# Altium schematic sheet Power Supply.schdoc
size 594 x 419 mm; Symbol: Drawing-Symbol_A4; @Project Name: Inverted_MAML_6x6; @Page Count: 5; @Update Date: 2026-08-04; @Create Date: 2026-08-04; @Schematic Name: Inverted_MAML; @Page No: 5; @Page Name: P1; Company: EasyEDA.com; Version: V1.0; Page Size: A4; Device: Drawing-Symbol_A4; @Create Time: 19:32:30; @Update Time: 19:32:30; Border: 1; Width: 2338; Height: 1652; Region Start: 1; X Region Count: 6; Y Region Count: 4; Blade Width: 10; Title Block Position: 3; @Board Name: Analog_Matrix
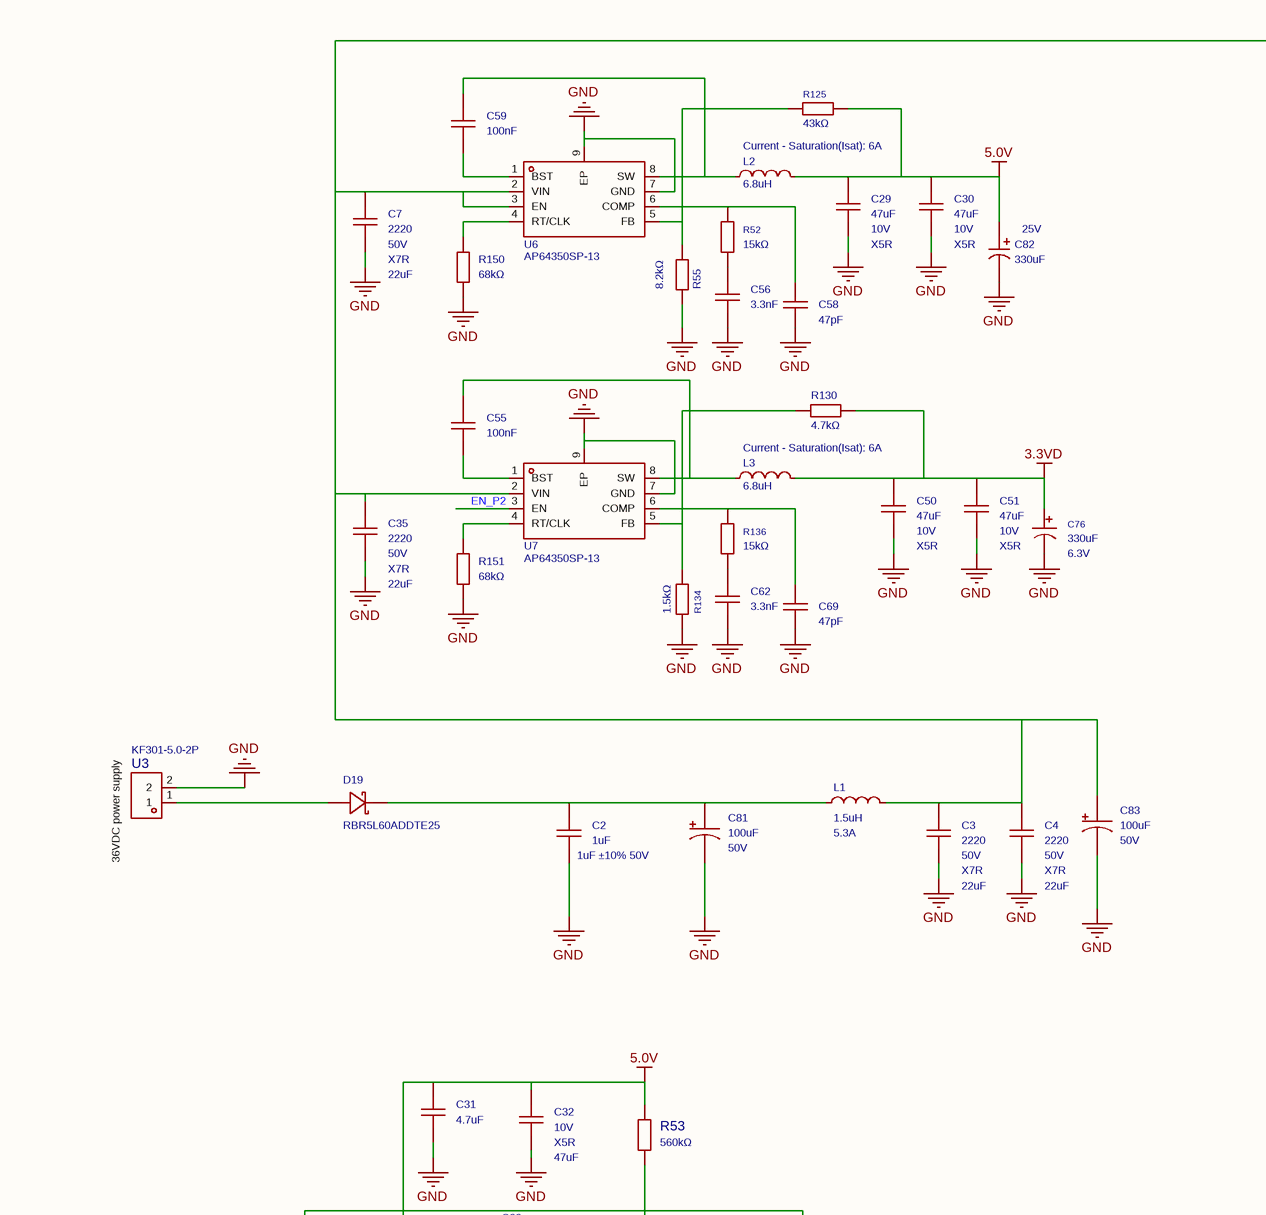
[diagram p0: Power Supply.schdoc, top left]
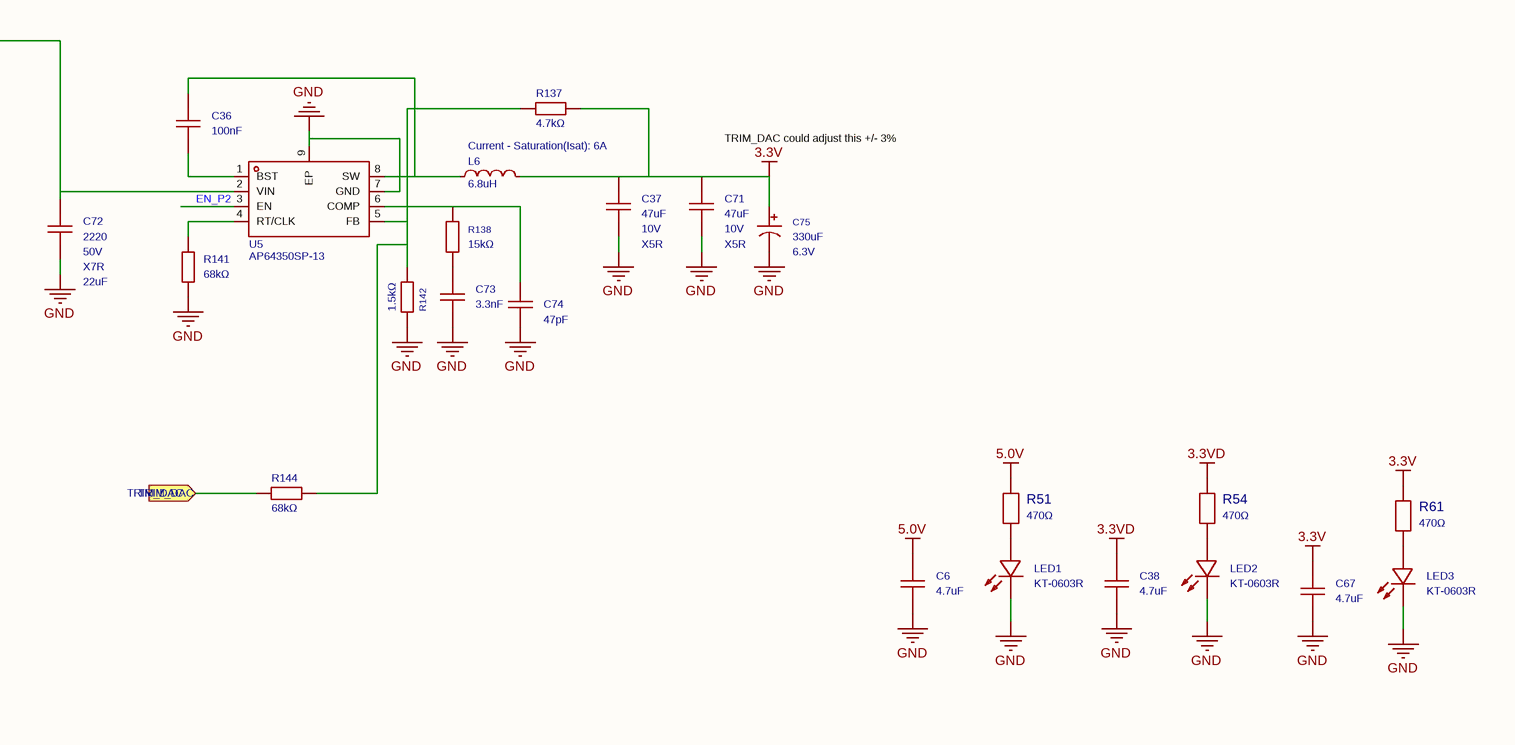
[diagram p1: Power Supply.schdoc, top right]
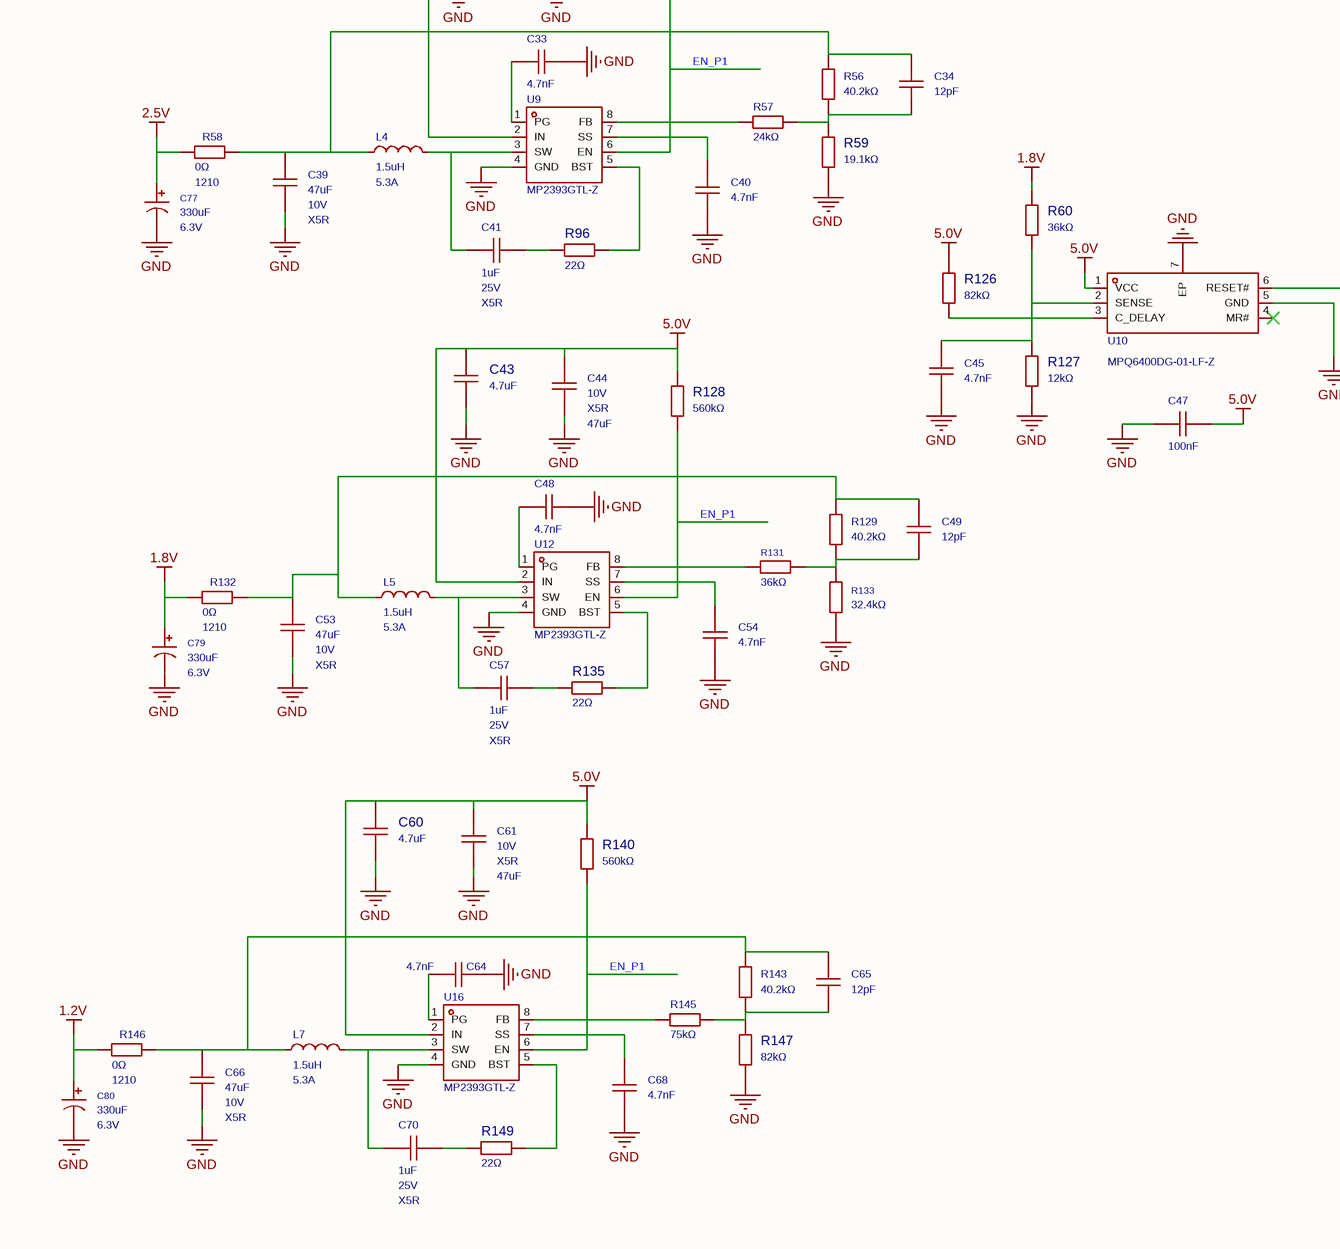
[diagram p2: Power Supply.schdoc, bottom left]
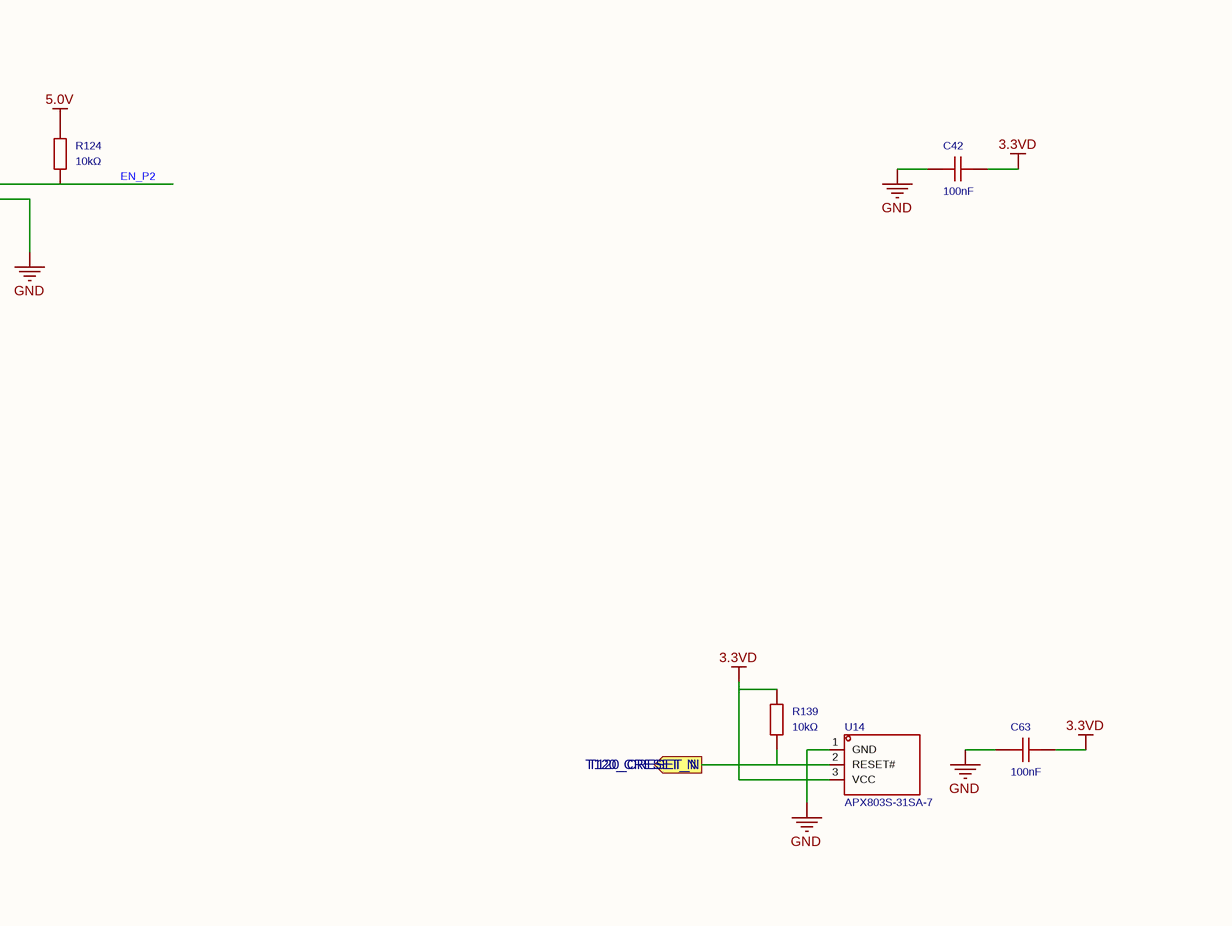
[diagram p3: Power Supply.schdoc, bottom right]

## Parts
C2  1uF  LCSC Part Name: 1uF ±10% 50V  [C1206]
C3  22uF  Supplier Footprint: 2220  Voltage Rating: 50V  Temperature Coefficient: X7R  [C2220]
C4  22uF  Supplier Footprint: 2220  Voltage Rating: 50V  Temperature Coefficient: X7R  [C2220]
C6  4.7uF  [C0402]
C7  22uF  Supplier Footprint: 2220  Voltage Rating: 50V  Temperature Coefficient: X7R  [C2220]
C29  47uF  Voltage Rating: 10V  Temperature Coefficient: X5R  [C1206]
C30  47uF  Voltage Rating: 10V  Temperature Coefficient: X5R  [C1206]
C31  4.7uF  [C0402]
C32  47uF  Voltage Rating: 10V  Temperature Coefficient: X5R  [C1206]
C33  4.7nF  [C0402]
C34  12pF  [C0402]
C35  22uF  Supplier Footprint: 2220  Voltage Rating: 50V  Temperature Coefficient: X7R  [C2220]
C36  100nF  [C0402]
C37  47uF  Voltage Rating: 10V  Temperature Coefficient: X5R  [C1206]
C38  4.7uF  [C0402]
C39  47uF  Voltage Rating: 10V  Temperature Coefficient: X5R  [C1206]
C40  4.7nF  [C0402]
C41  1uF  Voltage Rating: 25V  Temperature Coefficient: X5R  [C0402]
C42  100nF  [C0402]
C43  4.7uF  [C0402]
C44  47uF  Voltage Rating: 10V  Temperature Coefficient: X5R  [C1206]
C45  4.7nF  [C0402]
C47  100nF  [C0402]
C48  4.7nF  [C0402]
C49  12pF  [C0402]
C50  47uF  Voltage Rating: 10V  Temperature Coefficient: X5R  [C1206]
C51  47uF  Voltage Rating: 10V  Temperature Coefficient: X5R  [C1206]
C53  47uF  Voltage Rating: 10V  Temperature Coefficient: X5R  [C1206]
C54  4.7nF  [C0402]
C55  100nF  [C0402]
C56  3.3nF  [C0402]
C57  1uF  Voltage Rating: 25V  Temperature Coefficient: X5R  [C0402]
C58  47pF  [C0402]
C59  100nF  [C0402]
C60  4.7uF  [C0402]
C61  47uF  Voltage Rating: 10V  Temperature Coefficient: X5R  [C1206]
C62  3.3nF  [C0402]
C63  100nF  [C0402]
C64  4.7nF  [C0402]
C65  12pF  [C0402]
C66  47uF  Voltage Rating: 10V  Temperature Coefficient: X5R  [C1206]
C67  4.7uF  [C0402]
C68  4.7nF  [C0402]
C69  47pF  [C0402]
C70  1uF  Voltage Rating: 25V  Temperature Coefficient: X5R  [C0402]
C71  47uF  Voltage Rating: 10V  Temperature Coefficient: X5R  [C1206]
C72  22uF  Supplier Footprint: 2220  Voltage Rating: 50V  Temperature Coefficient: X7R  [C2220]
C73  3.3nF  [C0402]
C74  47pF  [C0402]
C75  330uF  Voltage Rating: 6.3V  [CAP-SMD_BD6.3-L6.6-W6.6-FD]
C76  330uF  Voltage Rating: 6.3V  [CAP-SMD_BD6.3-L6.6-W6.6-FD]
C77  330uF  Voltage Rating: 6.3V  [CAP-SMD_BD6.3-L6.6-W6.6-FD]
C79  330uF  Voltage Rating: 6.3V  [CAP-SMD_BD6.3-L6.6-W6.6-FD]
C80  330uF  Voltage Rating: 6.3V  [CAP-SMD_BD6.3-L6.6-W6.6-FD]
C81  100uF  Voltage Rating: 50V  [CAP-SMD_BD10.0-L10.3-W10.3-LS11.0-FD]
C82  330uF  Voltage Rating: 25V  [CAP-SMD_BD8.0-L8.3-W8.3-FD]
C83  100uF  Voltage Rating: 50V  [CAP-SMD_BD10.0-L10.3-W10.3-LS11.0-FD]
D19  RBR5L60ADDTE25  [SMA_L4.5-W2.6-LS5.0-RD]
L1  1.5uH  Current Rating: 5.3A  [IND-SMD_L7.8-W7.0_GCD75]
L2  6.8uH  Current - Saturation(Isat): 6A  [IND-SMD_L6.6-W6.6]
L3  6.8uH  Current - Saturation(Isat): 6A  [IND-SMD_L6.6-W6.6]
L4  1.5uH  Current Rating: 5.3A  [IND-SMD_L7.8-W7.0_GCD75]
L5  1.5uH  Current Rating: 5.3A  [IND-SMD_L7.8-W7.0_GCD75]
L6  6.8uH  Current - Saturation(Isat): 6A  [IND-SMD_L6.6-W6.6]
L7  1.5uH  Current Rating: 5.3A  [IND-SMD_L7.8-W7.0_GCD75]
LED1  KT-0603R  [LED0603-RD]
LED2  KT-0603R  [LED0603-RD]
LED3  KT-0603R  [LED0603-RD]
R51  470Ω  [R0402]
R52  15kΩ  [R0402]
R53  560kΩ  [R0402]
R54  470Ω  [R0402]
R55  8.2kΩ  [R0402]
R56  40.2kΩ  [R0402]
R57  24kΩ  [R0402]
R58  0Ω  Supplier Footprint: 1210  [R1210]
R59  19.1kΩ  [R0402]
R60  36kΩ  [R0402]
R61  470Ω  [R0402]
R96  22Ω  [R0402]
R124  10kΩ  [R0402]
R125  43kΩ  [R0402]
R126  82kΩ  [R0402]
R127  12kΩ  [R0402]
R128  560kΩ  [R0402]
R129  40.2kΩ  [R0402]
R130  4.7kΩ  [R0402]
R131  36kΩ  [R0402]
R132  0Ω  Supplier Footprint: 1210  [R1210]
R133  32.4kΩ  [R0402]
R134  1.5kΩ  [R0402]
R135  22Ω  [R0402]
R136  15kΩ  [R0402]
R137  4.7kΩ  [R0402]
R138  15kΩ  [R0402]
R139  10kΩ  [R0402]
R140  560kΩ  [R0402]
R141  68kΩ  [R0402]
R142  1.5kΩ  [R0402]
R143  40.2kΩ  [R0402]
R144  68kΩ  [R0402]
R145  75kΩ  [R0402]
R146  0Ω  Supplier Footprint: 1210  [R1210]
R147  82kΩ  [R0402]
R149  22Ω  [R0402]
R150  68kΩ  [R0402]
R151  68kΩ  [R0402]
U3  KF301-5.0-2P  [CONN-TH_P5.00_KF301-5.0-2P]
U5  AP64350SP-13  [SO-8_L4.9-W3.9-P1.27-LS6.0-BL-EP]
U6  AP64350SP-13  [SO-8_L4.9-W3.9-P1.27-LS6.0-BL-EP]
U7  AP64350SP-13  [SO-8_L4.9-W3.9-P1.27-LS6.0-BL-EP]
U9  MP2393GTL-Z  [SOT-583-8_L2.1-W1.2-P0.50-LS1.6-BL]
U10  MPQ6400DG-01-LF-Z  [QFN-6_L2.0-W2.0-P0.65-BL-EP]
U12  MP2393GTL-Z  [SOT-583-8_L2.1-W1.2-P0.50-LS1.6-BL]
U14  APX803S-31SA-7  [SOT-23-3_L2.9-W1.3-P1.90-LS2.4-BR]
U16  MP2393GTL-Z  [SOT-583-8_L2.1-W1.2-P0.50-LS1.6-BL]

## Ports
T120_CRESET_N (out), TRIM_DAC (in)

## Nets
1.2V: C80.1 R146.1
1.8V: C79.1 R60.2 R132.1
2.5V: C77.1 R58.1
3.3V: C37.2 C67.2 C71.2 C75.1 L6.2 R61.2 R137.1
3.3VD: C38.2 C42.1 C50.2 C51.2 C63.1 C76.1 L3.2 R54.2 R130.1 R139.2 U14.3(VCC)
5.0V: C6.2 C29.2 C30.2 C31.2 C32.2 C43.1 C44.2 C47.1 C60.1 C61.2 C82.1 L2.2 R51.2 R53.2 R124.2 R125.1 R126.2 R128.2 R140.2 U9.2(IN) U10.1(VCC) U12.2(IN) U16.2(IN)
GND: C2.1 C3.1 C4.1 C6.1 C7.1 C29.1 C30.1 C31.1 C32.1 C33.1 C35.1 C37.1 C38.1 C39.1 C40.1 C42.2 C43.2 C44.1 C45.1 C47.2 C48.1 C50.1 C51.1 C53.1 C54.1 C56.1 C58.1 C60.2 C61.1 C62.1 C63.2 C64.1 C66.1 C67.1 C68.1 C69.1 C71.1 C72.1 C73.1 C74.1 C75.2 C76.2 C77.2 C79.2 C80.2 C81.2 C82.2 C83.2 LED1.1(K) LED2.1(K) LED3.1(K) R55.1 R59.1 R127.1 R133.1 R134.1 R141.1 R142.1 R147.1 R150.1 R151.1 U3.2 U5.7(GND) U5.9(EP) U6.7(GND) U6.9(EP) U7.7(GND) U7.9(EP) U9.4(GND) U10.5(GND) U10.7(EP) U12.4(GND) U14.1(GND) U16.4(GND)
EN_P1: R53.1 R128.1 R140.1 U9.6(EN) U12.6(EN) U16.6(EN)
EN_P2: R124.1 U5.3(EN) U7.3(EN) U10.6(RESET#)
T120_CRESET_N: R139.1 U14.2(RESET#) ; port T120_CRESET_N
TRIM_DAC: R144.2 ; port TRIM_DAC
NetC2_2: C2.2 C81.1 D19.1(K) L1.1
NetC3_2: C3.2 C4.2 C7.2 C35.2 C72.2 C83.1 L1.2 U5.2(VIN) U6.2(VIN) U6.3(EN) U7.2(VIN)
NetC33_2: C33.2 U9.1(PG)
NetC34_1: C34.1 R56.1 R57.2 R59.2
NetC34_2: C34.2 C39.2 L4.1 R56.2 R58.2
NetC36_1: C36.1 L6.1 U5.8(SW)
NetC36_2: C36.2 U5.1(BST)
NetC40_2: C40.2 U9.7(SS)
NetC41_1: C41.1 L4.2 U9.3(SW)
NetC41_2: C41.2 R96.1
NetC45_2: C45.2 R60.1 R127.2 U10.2(SENSE)
NetC48_2: C48.2 U12.1(PG)
NetC49_1: C49.1 R129.1 R131.2 R133.2
NetC49_2: C49.2 C53.2 L5.1 R129.2 R132.2
NetC54_2: C54.2 U12.7(SS)
NetC55_1: C55.1 L3.1 U7.8(SW)
NetC55_2: C55.2 U7.1(BST)
NetC56_2: C56.2 R52.1
NetC57_1: C57.1 L5.2 U12.3(SW)
NetC57_2: C57.2 R135.1
NetC58_2: C58.2 R52.2 U6.6(COMP)
NetC59_1: C59.1 L2.1 U6.8(SW)
NetC59_2: C59.2 U6.1(BST)
NetC62_2: C62.2 R136.1
NetC64_2: C64.2 U16.1(PG)
NetC65_1: C65.1 R143.1 R145.2 R147.2
NetC65_2: C65.2 C66.2 L7.1 R143.2 R146.2
NetC68_2: C68.2 U16.7(SS)
NetC69_2: C69.2 R136.2 U7.6(COMP)
NetC70_1: C70.1 L7.2 U16.3(SW)
NetC70_2: C70.2 R149.1
NetC73_2: C73.2 R138.1
NetC74_2: C74.2 R138.2 U5.6(COMP)
NetD19_2: D19.2(A) U3.1
NetLED1_2: LED1.2(A) R51.1
NetLED2_2: LED2.2(A) R54.1
NetLED3_2: LED3.2(A) R61.1
NetR55_2: R55.2 R125.2 U6.5(FB)
NetR57_1: R57.1 U9.8(FB)
NetR96_2: R96.2 U9.5(BST)
NetR126_1: R126.1 U10.3(C_DELAY)
NetR130_2: R130.2 R134.2 U7.5(FB)
NetR131_1: R131.1 U12.8(FB)
NetR135_2: R135.2 U12.5(BST)
NetR137_2: R137.2 R142.2 R144.1 U5.5(FB)
NetR141_2: R141.2 U5.4(RT/CLK)
NetR145_1: R145.1 U16.8(FB)
NetR149_2: R149.2 U16.5(BST)
NetR150_2: R150.2 U6.4(RT/CLK)
NetR151_2: R151.2 U7.4(RT/CLK)

Not connected (* = marked no-connect by the designer): U10 4(MR#)*

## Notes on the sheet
- TRIM_DAC could adjust this +/- 3%
- (near U3) 36VDC power supply

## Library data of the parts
C2 = CL31B105KBHNNNE: Capacitance: Tolerance:±10% Tolerance:±10% Voltage Rated: Temperature Coefficient:; Manufacturer: SAMSUNG(三星); Check: true; 3D Model: c6790e9475e1483991d2c64340b24e96; 3D Model Transform: 125.984,62.992,0,0,0,0,0,0,0; Tolerance: ±10%; AddInBom: yes; ModelName: C1206_L3.2-W1.6-H1.3
C3 C4 C7 C35 C72 = FS55X226K500EHG: Capacitance:22uF Tolerance:±10% Tolerance:±10% Voltage Rating:50V Temperature Coefficient:X7R; Manufacturer: PSA(信昌电陶); Check: true; 3D Model: 9e21f3c1df46481da704b6d81ca75160; 3D Model Transform: 220.472,196.85,0,0,0,0,0,0,0; Tolerance: ±10%; AddInBom: yes; ModelName: C2220_L5.6-W5.0-H3.0
C6 C31 C38 C67 = CL05A475MP5NRNC: Capacitance:4.7uF Tolerance:±20% Tolerance:±20% Voltage Rating:10V Temperature Coefficient:X5R; Manufacturer: SAMSUNG(三星); Temperature Coefficient: X5R; Voltage Rating: 10V; 3D Model: b7d13df3e9464d7a99d0651d1a5b4d57; 3D Model Transform: 39.37,19.685,0,0,0,0,0,0,0; Tolerance: ±20%; AddInBom: yes; ModelName: C0402_L1.0-W0.5-H0.5
C29 C30 C32 C37 C39 C44 C50 C51 C53 C61 C66 C71 = CL31A476MPHNNNE: Capacitance:47uF Tolerance:±20% Tolerance:±20% Voltage Rating:10V Temperature Coefficient:X5R; Manufacturer: SAMSUNG(三星); 3D Model: c6790e9475e1483991d2c64340b24e96; 3D Model Transform: 125.984,62.992,0,0,0,0,0,0,0; Tolerance: ±20%; AddInBom: yes; ModelName: C1206_L3.2-W1.6-H1.3
C33 C40 C45 C48 C54 C64 C68 = 0402B472K500NT: Capacitance:4.7nF Tolerance:±10% Tolerance:±10% Voltage Rating:50V Temperature Coefficient:X7R; Manufacturer: FH(风华); Symbol: CGJ2B2X7R1H472K050BA; 3D Model: b7d13df3e9464d7a99d0651d1a5b4d57; 3D Model Transform: 39.37,19.685,0,0,0,0,0,0,0; Tolerance: ±10%; Voltage Rating: 50V; Temperature Coefficient: X7R; AddInBom: yes; ModelName: C0402_L1.0-W0.5-H0.5
C34 C49 C65 = V120J0402HQC500NBT: Capacitance:12pF Voltage Rating:50V Temperature Coefficient:C0G; Manufacturer: VIIYONG(微容); Check: true; 3D Model: b7d13df3e9464d7a99d0651d1a5b4d57; 3D Model Transform: 39.37,19.685,0,0,0,0,0,0,0; Voltage Rating: 50V; Temperature Coefficient: C0G; AddInBom: yes; ModelName: C0402_L1.0-W0.5-H0.5
C36 C42 C47 C55 C59 C63 = CL05B104KB54PNC: Capacitance: Tolerance:±10% Tolerance:±10% Voltage Rated: Temperature Coefficient:; Manufacturer: SAMSUNG(三星); Check: true; 3D Model: b7d13df3e9464d7a99d0651d1a5b4d57; 3D Model Transform: 39.37,19.685,0,0,0,0,0,0,0; Tolerance: ±10%; AddInBom: yes; ModelName: C0402_L1.0-W0.5-H0.5
C41 C57 C70 = CL05A105KA5NQNC: Capacitance:1uF Tolerance:±10% Tolerance:±10% Voltage Rating:25V Temperature Coefficient:X5R; Manufacturer: SAMSUNG(三星); 3D Model: b7d13df3e9464d7a99d0651d1a5b4d57; 3D Model Transform: 39.37,19.685,0,0,0,0,0,0,0; Tolerance: ±10%; AddInBom: yes; ModelName: C0402_L1.0-W0.5-H0.5
C43 C60 = CL05A475MP5NRNC: Capacitance:4.7uF Tolerance:±20% Tolerance:±20% Voltage Rating:10V Temperature Coefficient:X5R; Manufacturer: SAMSUNG(三星); Symbol: LMK105BBJ475MVLF; Temperature Coefficient: X5R; Voltage Rating: 10V; 3D Model: b7d13df3e9464d7a99d0651d1a5b4d57; 3D Model Transform: 39.37,19.685,0,0,0,0,0,0,0; Tolerance: ±20%; AddInBom: yes; ModelName: C0402_L1.0-W0.5-H0.5
C56 = CL05B332KB5NNNC: Capacitance:3.3nF Tolerance:±10% Tolerance:±10% Voltage Rating:50V Temperature Coefficient:X7R; Manufacturer: SAMSUNG(三星); AddInBom: yes; ModelId: b7d13df3e9464d7a99d0651d1a5b4d570819f05c4eef4c71ace90d822a990e87; ModelName: C0402_L1.0-W0.5-H0.5; ModelTransform: 39.37,19.685,0,0,0,0,0,0,0; Tolerance: ±10%; Voltage Rating: 50V; Temperature Coefficient: X7R
C58 = 0402CG470J500NT: Capacitance:47pF Tolerance:±5% Tolerance:±5% Voltage Rating:50V Temperature Coefficient:C0G; Manufacturer: FH(风华); AddInBom: yes; ModelId: b7d13df3e9464d7a99d0651d1a5b4d570819f05c4eef4c71ace90d822a990e87; ModelName: C0402_L1.0-W0.5-H0.5; ModelTransform: 39.37,19.685,0,0,0,0,0,0,0; Tolerance: ±5%; Voltage Rating: 50V; Temperature Coefficient: C0G
C62 C73 = CL05B332KB5NNNC: Capacitance:3.3nF Tolerance:±10% Tolerance:±10% Voltage Rating:50V Temperature Coefficient:X7R; Manufacturer: SAMSUNG(三星); 3D Model: b7d13df3e9464d7a99d0651d1a5b4d570819f05c4eef4c71ace90d822a990e87; 3D Model Transform: 39.37,19.685,0,0,0,0,0,0,0; Tolerance: ±10%; Voltage Rating: 50V; Temperature Coefficient: X7R; AddInBom: yes; ModelName: C0402_L1.0-W0.5-H0.5
C69 C74 = 0402CG470J500NT: Capacitance:47pF Tolerance:±5% Tolerance:±5% Voltage Rating:50V Temperature Coefficient:C0G; Manufacturer: FH(风华); 3D Model: b7d13df3e9464d7a99d0651d1a5b4d570819f05c4eef4c71ace90d822a990e87; 3D Model Transform: 39.37,19.685,0,0,0,0,0,0,0; Tolerance: ±5%; Voltage Rating: 50V; Temperature Coefficient: C0G; AddInBom: yes; ModelName: C0402_L1.0-W0.5-H0.5
C75-C77 C79 C80 = RVT0J331M0607_C58276: Capacitance:330uF Tolerance:±20% Tolerance:±20% Voltage Rating:6.3V Ripple Current:- Equivalent Series Resistance(ESR):- Diameter:6.3mm Height - Seated (Max):7.7mm Lifetime:2000hrs@105℃ Operating Temperature:-55℃~+105℃ Operating Temperature:-55℃~+105℃; Manufacturer: HONOR(荣誉); AddInBom: yes; ModelId: 344012e5740642d7a5fd19e3d7e886680819f05c4eef4c71ace90d822a990e87; ModelTransform: 307.086,259.842,0,180,0,0,0,0,0; Tolerance: ±20%
C81 C83 = MVK 50V100 M 10*10: Capacitance:100uF Tolerance:±20% Tolerance:±20% Voltage Rating:50V Ripple Current:310mA@120Hz Equivalent Series Resistance(ESR):- Diameter:10mm Height - Seated (Max):10mm Lifetime:2000hrs@105℃ Operating Temperature:-40℃~+105℃ Operating Temperature:-40℃~+1; Manufacturer: SAMYOUNG(韩国三莹); Symbol: MVK 50VC100 M; AddInBom: yes; ModelId: 44cb92e87a73435bbda93569417358d90819f05c4eef4c71ace90d822a990e87; ModelName: CAP-SMD_BD10.0-L10.3-W10.3-H10.2; ModelTransform: 405.511,456.692,0,90,0,0,-0.004,-0.001,0; Tolerance: ±20%
C82 = RVT1E331M0810 330UF 25V: Capacitance:330uF Tolerance:±20% Tolerance:±20% Voltage Rating:25V Ripple Current:228mA@120Hz Equivalent Series Resistance(ESR):- Diameter:8mm Height - Seated (Max):10.2mm Lifetime:2800hrs@105℃ Operating Temperature:-55℃~+105℃ Operating Temperature:-55℃~+; Manufacturer: DMBJ(振宝佳); AddInBom: yes; ModelId: 54702dd93fd341bcb1a25d0cb74ede280819f05c4eef4c71ace90d822a990e87; ModelTransform: 393.7,326.771,0,180,0,0,0,0,0; Tolerance: ±20%
D19 = RBR5L60ADDTE25: Manufacturer: ROHM(罗姆); 3D Model: 1df18568bd264f7b8aab0a09639f05cb; 3D Model Transform: 200.787,102.362,0,0,0,0,0,0,0; AddInBom: yes
L1 L4 L5 L7 = CD75-1R5M 1.5UH: Inductance:1.5uH Tolerance:±20% Tolerance:±20% Current Rating:5.3A DC Resistance(DCR):23mΩ Type:- Ratings:-; Manufacturer: DMBJ(振宝佳); 3D Model: 8c6194b56e1c4a4a93105af21067a6a4; 3D Model Transform: 307.086,275.59,0,0,0,0,0.001,0,0; Tolerance: ±20%; DC Resistance(DCR): 23mΩ; AddInBom: yes; ModelName: IND-SMD_L7.8-W7.0-H5.0_GCD75
L2 = SMMS0630-6R8M: Inductance:6.8uH Tolerance:±20% Tolerance:±20% Current Rating:- Current - Saturation(Isat):6A DC Resistance(DCR):48mΩ Type:Molded Inductor; Manufacturer: SXN(顺翔诺); AddInBom: yes; ModelId: 484d62df9f9b401e85d563d919dc12a20819f05c4eef4c71ace90d822a990e87; ModelTransform: 275.59,259.88137,0,0,0,0,0,0,0; Tolerance: ±20%; DC Resistance(DCR): 48mΩ
L3 L6 = SMMS0630-6R8M: Inductance:6.8uH Tolerance:±20% Tolerance:±20% Current Rating:- Current - Saturation(Isat):6A DC Resistance(DCR):48mΩ Type:Molded Inductor; Manufacturer: SXN(顺翔诺); 3D Model: 484d62df9f9b401e85d563d919dc12a20819f05c4eef4c71ace90d822a990e87; 3D Model Transform: 275.59,259.88137,0,0,0,0,0,0,0; Tolerance: ±20%; DC Resistance(DCR): 48mΩ; AddInBom: yes
LED1-LED3 = KT-0603R: Emitted Color:Red Power Dissipation:- Forward Current:- Dominant Wavelength:- Dominant Wavelength:- Peak Wavelength:- Diode Configuration:- Lens Color:- Color Temperature:- Color Temperature:- Viewing Angle:- Mounting Sytle:- Operating Temperature:-40℃~+8; Manufacturer: KENTO; 3D Model: 5e3b568068dd46cf8019c1d1baa0031b; 3D Model Transform: 63.7794,32.283,0,0,0,0,0,0,0; Emitted Color: Red; AddInBom: yes
R51 R54 R61 = 0402WGF4700TCE: Type:Thick Film Resistors Resistance: Tolerance:±1% Tolerance:±1% Power(Watts): Overload Voltage (Max): Temperature Coefficient:±100ppm/℃ Temperature Coefficient:±100ppm/℃ Operating Temperature Range:-55℃~+155℃ Operating Temperature Range:-55℃~+155℃; Manufacturer: UNI-ROYAL(厚声); Symbol: ERJ2RKF4700X; 3D Model: efdecb7dae4442949d28eecaf748420f; 3D Model Transform: 39.37,19.685,0,0,0,0,0,0,0; Tolerance: ±1%; AddInBom: yes; ModelName: R0402_L1.0-W0.5-H0.4
R52 = 0402WGF1502TCE: Type:Thick Film Resistors Resistance:15kΩ Tolerance:±1% Tolerance:±1% Power(Watts): Overload Voltage (Max): Temperature Coefficient:±100ppm/℃ Temperature Coefficient:±100ppm/℃ Operating Temperature Range:-55℃~+155℃ Operating Temperature Range:-55℃~+155℃; Manufacturer: UNI-ROYAL(厚声); AddInBom: yes; ModelId: efdecb7dae4442949d28eecaf748420f0819f05c4eef4c71ace90d822a990e87; ModelName: R0402_L1.0-W0.5-H0.4; ModelTransform: 39.37,19.685,0,0,0,0,0,0,0; Tolerance: ±1%
R53 R128 R140 = 0402WGF5603TCE: Type:Thick Film Resistor Resistance:560kΩ Tolerance:±1% Tolerance:±1% Power(Watts):62.5mW Voltage-Supply(Max):50V Temperature Coefficient:±100ppm/℃ Temperature Coefficient:±100ppm/℃ Operating Temperature:-55℃~+155℃ Operating Temperature:-55℃~+155℃; Manufacturer: UNI-ROYAL(厚声); 3D Model: efdecb7dae4442949d28eecaf748420f; 3D Model Transform: 39.37,19.685,0,0,0,0,0,0,0; Tolerance: ±1%; Power(Watts): 62.5mW; Voltage-Supply(Max): 50V; AddInBom: yes; ModelName: R0402_L1.0-W0.5-H0.4
R55 = CR0402FF8201G: Type:Thick Film Resistor Resistance:8.2kΩ Tolerance:±1% Tolerance:±1% Power(Watts):62.5mW Voltage-Supply(Max):50V Temperature Coefficient:±200ppm/℃ Temperature Coefficient:±200ppm/℃ Operating Temperature:-55℃~+125℃ Operating Temperature:-55℃~+125℃; Manufacturer: LIZ(丽智电子); AddInBom: yes; ModelId: efdecb7dae4442949d28eecaf748420f0819f05c4eef4c71ace90d822a990e87; ModelName: R0402_L1.0-W0.5-H0.4; ModelTransform: 39.37,19.685,0,0,0,0,0,0,0; Tolerance: ±1%; Power(Watts): 62.5mW; Voltage-Supply(Max): 50V
R56 R129 R143 = 0402WGF4022TCE: Type:Thick Film Resistor Resistance:40.2kΩ Tolerance:±1% Tolerance:±1% Power(Watts):62.5mW Voltage-Supply(Max):50V Temperature Coefficient:±100ppm/℃ Temperature Coefficient:±100ppm/℃ Operating Temperature:-55℃~+155℃ Operating Temperature:-55℃~+155℃; Manufacturer: UNI-ROYAL(厚声); 3D Model: efdecb7dae4442949d28eecaf748420f; 3D Model Transform: 39.37,19.685,0,0,0,0,0,0,0; Tolerance: ±1%; Power(Watts): 62.5mW; Voltage-Supply(Max): 50V; AddInBom: yes; ModelName: R0402_L1.0-W0.5-H0.4
R57 = 0402WGF2402TCE: Type:Thick Film Resistors Resistance:24kΩ Tolerance:±1% Tolerance:±1% Power(Watts): Overload Voltage (Max): Temperature Coefficient:±100ppm/℃ Temperature Coefficient:±100ppm/℃ Operating Temperature Range:-55℃~+155℃ Operating Temperature Range:-55℃~+155℃; Manufacturer: UNI-ROYAL(厚声); 3D Model: efdecb7dae4442949d28eecaf748420f; 3D Model Transform: 39.37,19.685,0,0,0,0,0,0,0; Tolerance: ±1%; AddInBom: yes; ModelName: R0402_L1.0-W0.5-H0.4
R58 R132 R146 = RS-1210000JT: Type:Thick Film Resistors Resistance:0Ω Tolerance:±5% Tolerance:±5% Power(Watts):1/3W Voltage-Supply(Max):200V Operating Temperature:-55℃~+155℃ Operating Temperature:-55℃~+155℃; Manufacturer: FH(风华); 3D Model: 20ff733cacdd4b0e91bc367113f3d8ae; 3D Model Transform: 125.984,102.362,0,0,0,0,0,0,0; Tolerance: ±5%; Power(Watts): 1/3W; Voltage-Supply(Max): 200V; AddInBom: yes; ModelName: R1210_L3.2-W2.6-H0.6
R59 = 0402WGF1912TCE: Type:Thick Film Resistor Resistance:19.1kΩ Tolerance:±1% Tolerance:±1% Power(Watts):62.5mW Voltage-Supply(Max):50V Temperature Coefficient:±100ppm/℃ Temperature Coefficient:±100ppm/℃ Operating Temperature:-55℃~+155℃ Operating Temperature:-55℃~+155℃; Manufacturer: UNI-ROYAL(厚声); 3D Model: efdecb7dae4442949d28eecaf748420f; 3D Model Transform: 39.37,19.685,0,0,0,0,0,0,0; Tolerance: ±1%; Power(Watts): 62.5mW; Voltage-Supply(Max): 50V; AddInBom: yes; ModelName: R0402_L1.0-W0.5-H0.4
R60 R131 = 0402WGJ0363TCE: Type:Thick Film Resistors Resistance:36kΩ Tolerance:±5% Tolerance:±5% Power(Watts): Overload Voltage (Max): Temperature Coefficient:±100ppm/℃ Temperature Coefficient:±100ppm/℃ Operating Temperature Range:-55℃~+155℃ Operating Temperature Range:-55℃~+155℃; Manufacturer: UNI-ROYAL(厚声); 3D Model: efdecb7dae4442949d28eecaf748420f; 3D Model Transform: 39.37,19.685,0,0,0,0,0,0,0; Tolerance: ±5%; AddInBom: yes; ModelName: R0402_L1.0-W0.5-H0.4
R96 R135 R149 = 0402WGF220JTCE: Type:Thick Film Resistors Resistance:22Ω Tolerance:±1% Tolerance:±1% Power(Watts): Overload Voltage (Max): Temperature Coefficient:±100ppm/℃ Temperature Coefficient:±100ppm/℃ Operating Temperature Range:-55℃~+155℃ Operating Temperature Range:-55℃~+155℃; Manufacturer: UNI-ROYAL(厚声); 3D Model: efdecb7dae4442949d28eecaf748420f; 3D Model Transform: 39.37,19.685,0,0,0,0,0,0,0; Tolerance: ±1%; AddInBom: yes; ModelName: R0402_L1.0-W0.5-H0.4
R124 R139 = 0402WGF1002TCE: Type:Thick Film Resistors Resistance:10kΩ Tolerance:±1% Tolerance:±1% Power(Watts): Overload Voltage (Max): Temperature Coefficient:±100ppm/℃ Temperature Coefficient:±100ppm/℃ Operating Temperature Range:-55℃~+155℃ Operating Temperature Range:-55℃~+155℃; Manufacturer: UNI-ROYAL(厚声); Add into BOM: yes; 3D Model: efdecb7dae4442949d28eecaf748420f; 3D Model Transform: 39.37,19.685,0,0,0,0,0,0,0; Tolerance: ±1%; ModelName: R0402_L1.0-W0.5-H0.4
R125 = 0402WGJ0433TCE: Type:Thick Film Resistor Resistance:43kΩ Tolerance:±5% Tolerance:±5% Power(Watts):62.5mW Voltage-Supply(Max):50V Temperature Coefficient:±100ppm/℃ Temperature Coefficient:±100ppm/℃ Operating Temperature:-55℃~+155℃ Operating Temperature:-55℃~+155℃; Manufacturer: UNI-ROYAL(厚声); AddInBom: yes; ModelId: efdecb7dae4442949d28eecaf748420f0819f05c4eef4c71ace90d822a990e87; ModelName: R0402_L1.0-W0.5-H0.4; ModelTransform: 39.37,19.685,0,0,0,0,0,0,0; Tolerance: ±5%; Power(Watts): 62.5mW; Voltage-Supply(Max): 50V
R126 R147 = 0402WGF8202TCE: Type:Thick Film Resistors Resistance:82kΩ Tolerance:±1% Tolerance:±1% Power(Watts):1/16W Voltage-Supply(Max):50V Temperature Coefficient:±100ppm/℃ Temperature Coefficient:±100ppm/℃ Operating Temperature:-55℃~+155℃ Operating Temperature:-55℃~+155℃; Manufacturer: UNI-ROYAL(厚声); 3D Model: efdecb7dae4442949d28eecaf748420f; 3D Model Transform: 39.37,19.685,0,0,0,0,0,0,0; Tolerance: ±1%; Power(Watts): 1/16W; Voltage-Supply(Max): 50V; AddInBom: yes; ModelName: R0402_L1.0-W0.5-H0.4
R127 = 0402WGJ0123TCE: Type:Thick Film Resistor Resistance:12kΩ Tolerance:±5% Tolerance:±5% Power(Watts):62.5mW Voltage-Supply(Max):50V Temperature Coefficient:±100ppm/℃ Temperature Coefficient:±100ppm/℃ Operating Temperature:-55℃~+155℃ Operating Temperature:-55℃~+155℃; Manufacturer: UNI-ROYAL(厚声); 3D Model: efdecb7dae4442949d28eecaf748420f; 3D Model Transform: 39.37,19.685,0,0,0,0,0,0,0; Tolerance: ±5%; Power(Watts): 62.5mW; Voltage-Supply(Max): 50V; AddInBom: yes; ModelName: R0402_L1.0-W0.5-H0.4
R130 R137 = 0402WGF4701TCE: Type:Thick Film Resistors Resistance:4.7kΩ Tolerance:±1% Tolerance:±1% Power(Watts): Overload Voltage (Max): Temperature Coefficient:±100ppm/℃ Temperature Coefficient:±100ppm/℃ Operating Temperature Range:-55℃~+155℃ Operating Temperature Range:-55℃~+155℃; Manufacturer: UNI-ROYAL(厚声); Symbol: RT0402BRD074K7L; 3D Model: efdecb7dae4442949d28eecaf748420f0819f05c4eef4c71ace90d822a990e87; 3D Model Transform: 39.37,19.685,0,0,0,0,0,0,0; Tolerance: ±1%; Power(Watts): 62.5mW; Voltage-Supply(Max): 50V; AddInBom: yes; ModelName: R0402_L1.0-W0.5-H0.4
R133 = 0402WGF3242TCE: Type:Thick Film Resistor Resistance:32.4kΩ Tolerance:±1% Tolerance:±1% Power(Watts):62.5mW Voltage-Supply(Max):50V Temperature Coefficient:±100ppm/℃ Temperature Coefficient:±100ppm/℃ Operating Temperature:-55℃~+155℃ Operating Temperature:-55℃~+155℃; Manufacturer: UNI-ROYAL(厚声); 3D Model: efdecb7dae4442949d28eecaf748420f; 3D Model Transform: 39.37,19.685,0,0,0,0,0,0,0; Tolerance: ±1%; Power(Watts): 62.5mW; Voltage-Supply(Max): 50V; AddInBom: yes; ModelName: R0402_L1.0-W0.5-H0.4
R134 R142 = 0402WGF1501TCE: Type:Thick Film Resistors Resistance:1.5kΩ Tolerance:±1% Tolerance:±1% Power(Watts): Overload Voltage (Max): Temperature Coefficient:±100ppm/℃ Temperature Coefficient:±100ppm/℃ Operating Temperature Range:-55℃~+155℃ Operating Temperature Range:-55℃~+155℃; Manufacturer: UNI-ROYAL(厚声); 3D Model: efdecb7dae4442949d28eecaf748420f0819f05c4eef4c71ace90d822a990e87; 3D Model Transform: 39.37,19.685,0,0,0,0,0,0,0; Tolerance: ±1%; AddInBom: yes; ModelName: R0402_L1.0-W0.5-H0.4
R136 R138 = 0402WGF1502TCE: Type:Thick Film Resistors Resistance:15kΩ Tolerance:±1% Tolerance:±1% Power(Watts): Overload Voltage (Max): Temperature Coefficient:±100ppm/℃ Temperature Coefficient:±100ppm/℃ Operating Temperature Range:-55℃~+155℃ Operating Temperature Range:-55℃~+155℃; Manufacturer: UNI-ROYAL(厚声); 3D Model: efdecb7dae4442949d28eecaf748420f0819f05c4eef4c71ace90d822a990e87; 3D Model Transform: 39.37,19.685,0,0,0,0,0,0,0; Tolerance: ±1%; AddInBom: yes; ModelName: R0402_L1.0-W0.5-H0.4
R141 R144 = 0402WGF6802TCE: Type:Thick Film Resistors Resistance:68kΩ Tolerance:±1% Tolerance:±1% Power(Watts): Overload Voltage (Max): Temperature Coefficient:±100ppm/℃ Temperature Coefficient:±100ppm/℃ Operating Temperature Range:-55℃~+155℃ Operating Temperature Range:-55℃~+155℃; Manufacturer: UNI-ROYAL(厚声); 3D Model: efdecb7dae4442949d28eecaf748420f0819f05c4eef4c71ace90d822a990e87; 3D Model Transform: 39.37,19.685,0,0,0,0,0,0,0; Tolerance: ±1%; AddInBom: yes; ModelName: R0402_L1.0-W0.5-H0.4
R145 = 0402WGF7502TCE: Type:Thick Film Resistor Resistance:75kΩ Tolerance:±1% Tolerance:±1% Power(Watts):62.5mW Voltage-Supply(Max):50V Temperature Coefficient:±100ppm/℃ Temperature Coefficient:±100ppm/℃ Operating Temperature:-55℃~+155℃ Operating Temperature:-55℃~+155℃; Manufacturer: UNI-ROYAL(厚声); 3D Model: efdecb7dae4442949d28eecaf748420f; 3D Model Transform: 39.37,19.685,0,0,0,0,0,0,0; Tolerance: ±1%; Power(Watts): 62.5mW; Voltage-Supply(Max): 50V; AddInBom: yes; ModelName: R0402_L1.0-W0.5-H0.4
R150 R151 = 0402WGF6802TCE: Type:Thick Film Resistors Resistance:68kΩ Tolerance:±1% Tolerance:±1% Power(Watts): Overload Voltage (Max): Temperature Coefficient:±100ppm/℃ Temperature Coefficient:±100ppm/℃ Operating Temperature Range:-55℃~+155℃ Operating Temperature Range:-55℃~+155℃; Manufacturer: UNI-ROYAL(厚声); AddInBom: yes; ModelId: efdecb7dae4442949d28eecaf748420f0819f05c4eef4c71ace90d822a990e87; ModelName: R0402_L1.0-W0.5-H0.4; ModelTransform: 39.37,19.685,0,0,0,0,0,0,0; Tolerance: ±1%
U3 = KF301-5.0-2P: Structure:1x2P Pitch:5mm Color:Blue Mounting Style:Straight Current Rating (Max):17A Voltage Rating (Max):250V Number of Pins:2P Number of Rows:1 Wire Gauge - AWG:14~22 Wire Gauge - AWG:14~22 Wire Gauge - mm2:1.5 Wire Gauge - mm2:1.5 Number of PINs Per Ro; Manufacturer: KEFA(科发); 3D Model: ccfba28652874fb7a69eea8ba34eb61b; 3D Model Transform: 417.322,299.21594,0,0,0,0,11.811,7.874,-137.795; Structure: 1x2P; Pitch: 5mm; Current Rating (Max): 17A; Voltage Rating (Max): 250V; Wire Gauge - AWG: 14~22; Wire Gauge - mm2: 1.5; Number of PINs Per Row: 2; AddInBom: yes
U5 = AP64350SP-13: Function:Step-down type Voltage - Supply:3.8V~40V Voltage - Supply:3.8V~40V Output Voltage:800mV~39V Output Voltage:800mV~39V Output Current:3.5A Frequency - Switching:100kHz~2.2MHz Frequency - Switching:100kHz~2.2MHz Operating Temperature:-40℃~+125℃ Oper; Manufacturer: DIODES(美台); 3D Model: 548305ef4d1f4879a4f47128885951540819f05c4eef4c71ace90d822a990e87; 3D Model Transform: 240.39054,192.913,0,270,0,0,0.004,-0.002,0; Output Current: 3.5A; Synchronous Rectifier: Yes; Number of Outputs: 1; Topology: Buck; Quiescent Current: 22uA; Switch tube (built-in/external): Built-in; Output Type: Adjustable; ModelName: SO-8_L4.9-W3.9-H1.5-LS5.9-P1.27
U6 U7 = AP64350SP-13: Function:Step-down type Voltage - Supply:3.8V~40V Voltage - Supply:3.8V~40V Output Voltage:800mV~39V Output Voltage:800mV~39V Output Current:3.5A Frequency - Switching:100kHz~2.2MHz Frequency - Switching:100kHz~2.2MHz Operating Temperature:-40℃~+125℃ Oper; Manufacturer: DIODES(美台); AddInBom: yes; ModelId: 548305ef4d1f4879a4f47128885951540819f05c4eef4c71ace90d822a990e87; ModelName: SO-8_L4.9-W3.9-H1.5-LS5.9-P1.27; ModelTransform: 240.39054,192.913,0,270,0,0,0.004,-0.002,0; Output Current: 3.5A; Number of Outputs: 1; Topology: Buck; Quiescent Current: 22uA; Switch tube (built-in/external): Built-in; Output Type: Adjustable
U9 U12 U16 = MP2393GTL-Z: Function:Buck Voltage - Supply:4.2V~24V Voltage - Supply:4.2V~24V Output Voltage:800mV~13V Output Voltage:800mV~13V Output Current:3A Frequency - Switching:650kHz Frequency - Switching:650kHz Operating Temperature:-40℃~+125℃@(TJ) Operating Temperature:-40; Manufacturer: MPS(芯源); 3D Model: 02e75bf59f984e50a34119cd31e52c94; 3D Model Transform: 82.677,62.992,0,0,0,0,0,0,0; Function: Buck; Output Current: 3A; Frequency - Switching: 650kHz; Synchronous Rectifier: Yes; Number of Outputs: 1; Quiescent Current: 200uA; Switch tube (built-in/external): Built-In; Output Type: Adjustable
U10 = MPQ6400DG-01-LF-Z: ChipType:Voltage monitor Output Type:Open Drain Voltage - Supply:1.8V~5.5V Voltage - Supply:1.8V~5.5V Reset Active Level:Active Low Number of Voltages Monitored:1 Manual Reset:Yes Watchdog:None Reset Timeout:24ms Operating Temperature:-40℃~+125℃@(Tj) Oper; 3D Model: 3ecf89f506624876bdd34225b53a96af; 3D Model Transform: 78.74,77.961,0,90,0,0,0,0,0; Number of Voltages Monitored: 1; Manual Reset: Yes; Watchdog: None; Reset Timeout: 24ms; Add into BOM: no; ModelName: QFN-6_L2.0-W2.0-H0.8-P0.65
U14 = APX803S-31SA-7: ChipType:Voltage Monitor Output Type:Open Drain Voltage - Supply:1V~5.5V Voltage - Supply:1V~5.5V Reset Active Level:Active Low Threshold Voltage:3.08V Number of Voltages Monitored:1 Manual Reset:No Watchdog:No Reset Timeout:240ms Operating Temperature:-4; Manufacturer: DIODES(美台); 3D Model: 62a57c6760504a01965db6419a6d07df; 3D Model Transform: 98.425,114.173,0,180,0,0,0.0005,-0.0005,0; Threshold Voltage: 3.08V; Number of Voltages Monitored: 1; Manual Reset: No; Reset Timeout: 240ms; AddInBom: yes; ModelName: SOT-23-3P_L2.9-W1.3-H1.0-LS2.4-P0.95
